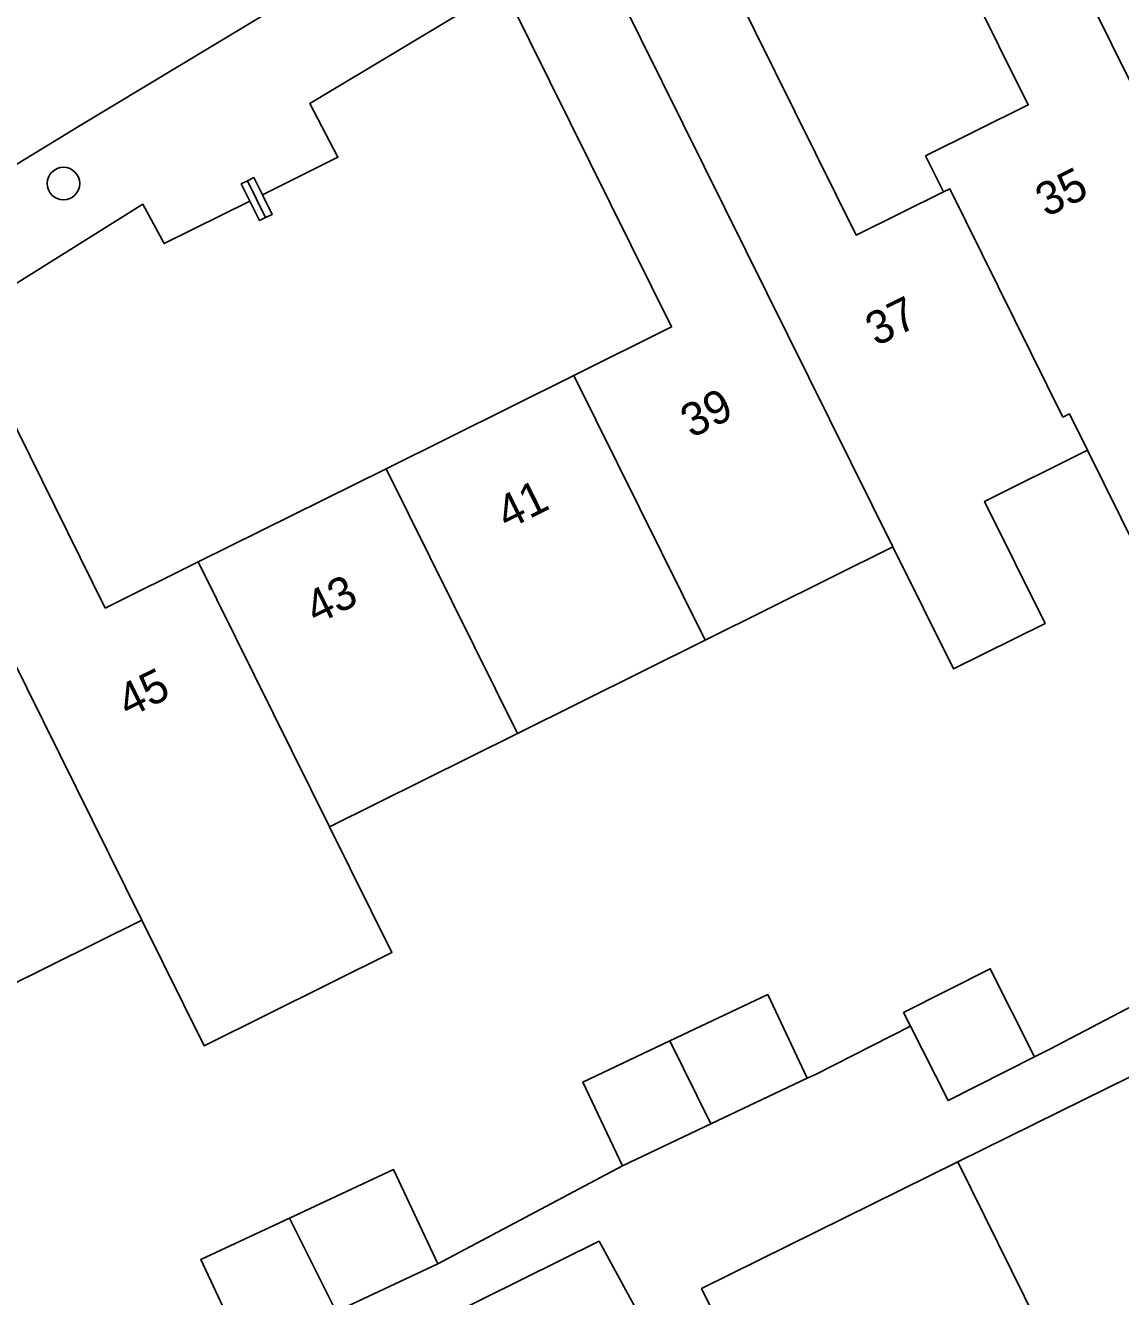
# Model space of a CAD drawing. Extents: x 157793 to 159380, y 380877 to 382313.
# Drawn here: x 158185.6 to 158218.59, y 381547.41 to 381585.69 of the extents above; entities that cross this region are included whole.
import ezdxf

# ---------------------------------------------------------------- set-up
doc = ezdxf.new("R2010")
doc.units = 0
for name, color, linetype in [('IMGEO_Boom', 7, 'Continuous'), ('IMGEO_Erf', 7, 'Continuous'), ('IMGEO_Pand', 7, 'Continuous'), ('IMGEO_Pand_nummerreeks', 7, 'Continuous'), ('IMGEO_Parkeervlak_open', 7, 'Continuous'), ('IMGEO_Rijbaan_lokaal_open', 7, 'Continuous'), ('IMGEO_Voetpad_open', 7, 'Continuous')]:
    doc.layers.add(name, color=color, linetype=linetype)

msp = doc.modelspace()

# ---------------------------------------------------------------- linework, layer by layer
at = {"layer": 'IMGEO_Boom'}
msp.add_circle((158186.745, 381580.929), 0.489, dxfattribs=at)
at = {"layer": 'IMGEO_Erf'}
for points in [[(158205.731, 381589.238), (158210.627, 381579.376), (158213.251, 381580.679), (158212.715, 381581.759), (158215.809, 381583.295), (158211.381, 381592.214)], [(158199.883, 381586.769), (158194.165, 381583.344), (158195.01, 381581.722), (158192.737, 381580.592), (158193.03, 381580.001), (158192.833, 381579.903), (158192.649, 381579.812), (158192.355, 381580.402), (158189.782, 381579.123), (158189.131, 381580.308), (158173.291, 381570.394), (158170.24, 381568.466), (158162.238, 381563.179), (158162.478, 381562.597), (158165.214, 381557.087), (158162.451, 381555.716), (158160.643, 381559.359), (158160.579, 381559.489)], [(158184.219, 381575.791), (158188.005, 381568.143), (158190.806, 381569.534), (158196.462, 381572.342), (158202.118, 381575.151), (158205.065, 381576.614), (158200.169, 381586.477)], [(158219.1, 381569.859), (158217.592, 381572.897), (158214.492, 381571.358), (158216.315, 381567.686), (158213.553, 381566.314), (158211.729, 381569.986), (158206.074, 381567.178), (158200.418, 381564.369), (158194.762, 381561.561), (158196.641, 381557.774), (158190.985, 381554.966), (158189.105, 381558.752), (158183.575, 381556.006), (158184.647, 381553.847), (158178.864, 381550.976), (158173.207, 381548.167), (158167.56, 381545.363)], [(158192.218, 381545.678), (158190.883, 381548.525), (158193.557, 381549.778), (158196.684, 381551.244), (158198.018, 381548.397), (158203.583, 381551.352), (158202.39, 381553.873), (158205.011, 381555.113), (158207.959, 381556.508), (158209.152, 381553.988), (158209.379, 381554.095), (158212.263, 381555.551), (158212.053, 381555.967), (158214.66, 381557.284), (158215.999, 381554.634), (158216.482, 381554.878), (158221.653, 381557.588)], [(158216.498, 381545.777), (158213.685, 381551.469), (158205.967, 381547.655), (158210.184, 381539.186)], [(158207.134, 381541.279), (158202.879, 381549.08), (158188.826, 381542.116)]]:
    msp.add_lwpolyline(points, dxfattribs=at)
at = {"layer": 'IMGEO_Pand'}
for points in [[(158224.704, 381572.641), (158230.365, 381575.451), (158228.311, 381579.587), (158224.361, 381587.542), (158221.315, 381586.03), (158216.886, 381594.948), (158214.125, 381593.577), (158222.498, 381576.701), (158222.651, 381576.777)], [(158224.704, 381572.641), (158222.651, 381576.777), (158222.498, 381576.701), (158214.125, 381593.577), (158211.473, 381592.26), (158211.381, 381592.214), (158215.809, 381583.295), (158212.715, 381581.759), (158213.251, 381580.679), (158213.444, 381580.775), (158216.851, 381573.899), (158217.045, 381573.995), (158217.592, 381572.897), (158219.1, 381569.859)], [(158211.729, 381569.986), (158213.553, 381566.314), (158216.315, 381567.686), (158214.492, 381571.358), (158217.592, 381572.897), (158217.045, 381573.995), (158216.851, 381573.899), (158213.444, 381580.775), (158213.251, 381580.679), (158210.627, 381579.376), (158205.731, 381589.238), (158202.88, 381587.823)], [(158206.074, 381567.178), (158211.729, 381569.986), (158202.88, 381587.823), (158200.169, 381586.477), (158205.065, 381576.614), (158202.118, 381575.151)], [(158192.833, 381579.903), (158192.285, 381581.01), (158192.1, 381580.918), (158192.355, 381580.402), (158192.649, 381579.812)], [(158192.285, 381581.01), (158192.833, 381579.903), (158193.03, 381580.001), (158192.737, 381580.592), (158192.481, 381581.107)], [(158190.806, 381569.534), (158188.005, 381568.143), (158184.219, 381575.791), (158181.614, 381574.497), (158181.347, 381575.034), (158180.966, 381574.845), (158181.233, 381574.308), (158181.515, 381573.739), (158181.698, 381573.83), (158183.16, 381570.734), (158189.105, 381558.752), (158190.985, 381554.966), (158196.641, 381557.774), (158194.762, 381561.561)], [(158206.074, 381567.178), (158202.118, 381575.151), (158196.462, 381572.342), (158200.418, 381564.369)], [(158190.806, 381569.534), (158194.762, 381561.561), (158200.418, 381564.369), (158196.462, 381572.342)], [(158183.575, 381556.006), (158189.105, 381558.752), (158183.16, 381570.734), (158180.337, 381569.332), (158182.331, 381565.316), (158179.413, 381563.867), (158180.503, 381561.671), (158180.676, 381561.757)], [(158212.053, 381555.967), (158212.263, 381555.551), (158213.391, 381553.317), (158215.999, 381554.634), (158214.66, 381557.284)], [(158205.011, 381555.113), (158206.25, 381552.614), (158209.152, 381553.988), (158207.959, 381556.508)], [(158224.05, 381556.591), (158219.568, 381554.376), (158216.743, 381552.98), (158213.685, 381551.469), (158216.498, 381545.777), (158219.556, 381547.288), (158219.62, 381547.158), (158232.238, 381553.507), (158230.878, 381556.259), (158225.522, 381553.612)], [(158205.011, 381555.113), (158202.39, 381553.873), (158203.583, 381551.352), (158206.25, 381552.614)], [(158194.955, 381546.961), (158198.018, 381548.397), (158196.684, 381551.244), (158193.557, 381549.778)], [(158194.955, 381546.961), (158193.557, 381549.778), (158190.883, 381548.525), (158192.218, 381545.678)]]:
    msp.add_lwpolyline(points, close=True, dxfattribs=at)
at = {"layer": 'IMGEO_Parkeervlak_open'}
msp.add_arc((159028.908, 380209.383), 1615.869, 121.063667, 122.005164, dxfattribs=at)
at = {"layer": 'IMGEO_Rijbaan_lokaal_open'}
msp.add_lwpolyline([(158183.619, 381580.473), (158187.198, 381582.647), (158193.298, 381586.323), (158197.442, 381588.804), (158204.527, 381592.945), (158208.404, 381595.207), (158215.342, 381599.166), (158212.758, 381603.678), (158212.456, 381603.502), (158211.849, 381603.172)], dxfattribs=at)
msp.add_arc((159028.908, 380209.383), 1615.869, 121.063667, 122.005164, dxfattribs=at)
at = {"layer": 'IMGEO_Voetpad_open'}
for points in [[(158216.163, 381599.634), (158215.342, 381599.166), (158208.404, 381595.207), (158204.527, 381592.945), (158197.442, 381588.804), (158193.298, 381586.323), (158187.198, 381582.647), (158183.619, 381580.473), (158176.194, 381575.813), (158172.404, 381573.353), (158164.9, 381568.534), (158161.399, 381566.209)], [(158194.165, 381583.344), (158199.883, 381586.769), (158199.732, 381587.041), (158204.907, 381590.073), (158205.095, 381589.838), (158210.945, 381593.215), (158211.473, 381592.26), (158214.125, 381593.577), (158216.886, 381594.948), (158219.989, 381596.506), (158220.86, 381596.956), (158220.214, 381598.29)], [(158160.579, 381559.489), (158159.716, 381561.226), (158162.478, 381562.597), (158162.238, 381563.179), (158170.24, 381568.466), (158173.291, 381570.394), (158189.131, 381580.308), (158189.782, 381579.123), (158192.355, 381580.402), (158192.1, 381580.918), (158192.285, 381581.01), (158192.481, 381581.107), (158192.737, 381580.592), (158195.01, 381581.722), (158194.165, 381583.344)], [(158221.653, 381557.588), (158216.482, 381554.878), (158215.999, 381554.634), (158213.391, 381553.317), (158212.263, 381555.551), (158209.379, 381554.095), (158209.152, 381553.988), (158206.25, 381552.614), (158203.583, 381551.352), (158198.018, 381548.397), (158194.955, 381546.961)], [(158210.184, 381539.186), (158205.967, 381547.655), (158213.685, 381551.469), (158216.743, 381552.98), (158219.568, 381554.376)], [(158188.826, 381542.116), (158202.879, 381549.08), (158207.134, 381541.279)]]:
    msp.add_lwpolyline(points, dxfattribs=at)

# ---------------------------------------------------------------- texts
at = {"layer": 'IMGEO_Pand_nummerreeks'}
for s, rotation, p in [('35', 26.4019, (158216.351, 381579.903)), ('37', 26.4076, (158211.23, 381576.015)), ('39', 26.4038, (158205.663, 381573.25)), ('41', 26.4068, (158200.11, 381570.492)), ('43', 26.4068, (158194.352, 381567.634)), ('45', 26.4076, (158188.695, 381564.825))]:
    msp.add_text(s, height=1, rotation=rotation, dxfattribs=at).set_placement(p)

doc.saveas('drawing.dxf')
